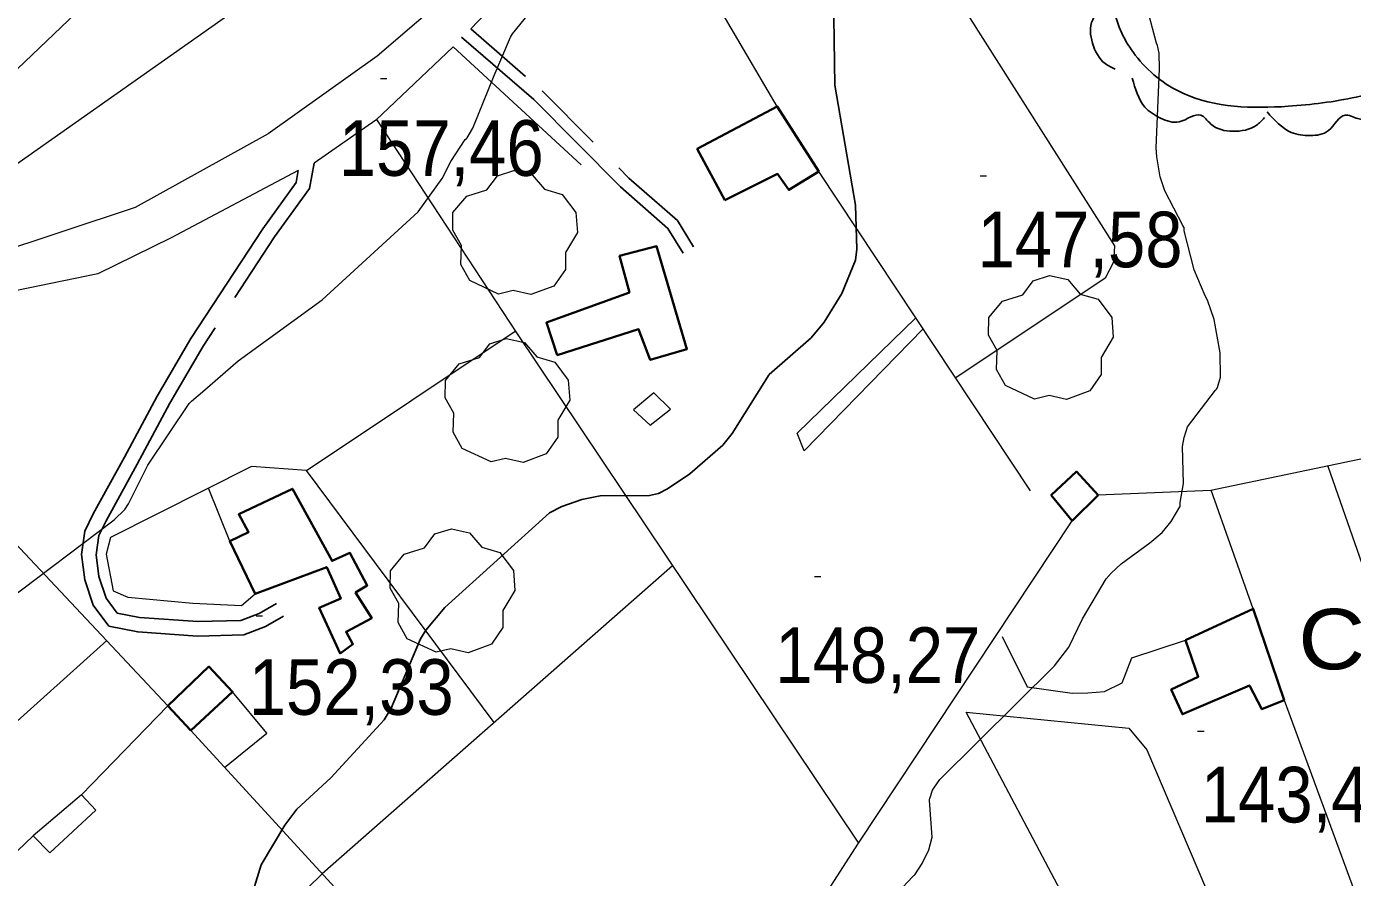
# Model space of a CAD drawing. Extents: x 480269 to 484877, y 4383588 to 4386804.
# Drawn here: x 481094.5 to 481302.9, y 4386070.7 to 4386204.5 of the extents above; entities that cross this region are included whole.
import ezdxf

# ---------------------------------------------------------------- set-up
doc = ezdxf.new("R2010")
doc.units = 0
doc.header["$LTSCALE"] = 3.8
doc.linetypes.add('MEDIUM_DASHED', pattern=[4.5, 3, -1.5])
for name, color, linetype, lineweight in [('27', 7, 'Continuous', 25), ('29', 7, 'Continuous', 13), ('38', 7, 'Continuous', 25), ('47', 7, 'Continuous', 35), ('51', 7, 'Continuous', 13), ('7', 7, 'Continuous', 13), ('8', 7, 'Continuous', 25), ('9', 7, 'Continuous', 13)]:
    doc.layers.add(name, color=color, linetype=linetype, lineweight=lineweight)
doc.layers.add('5', color=7, linetype='Continuous')

msp = doc.modelspace()

# ---------------------------------------------------------------- linework, layer by layer
at = {"layer": '27'}
for points in [[(481320.35, 4386227.93), (481327.1, 4386209.36), (481329.69, 4386201.13), (481328.04, 4386199.61), (481317.88, 4386196.87), (481303.46, 4386193.44), (481292.76, 4386192), (481276.23, 4386194.04), (481268.74, 4386200.02), (481265.37, 4386207.33), (481265.15, 4386217.97), (481261.89, 4386231.76), (481257.97, 4386240.94), (481250.26, 4386263.55), (481243.38, 4386282.87), (481238.59, 4386293.38), (481231.16, 4386310.07), (481228.43, 4386322.5), (481233.94, 4386332.68), (481243.59, 4386341.49), (481255.64, 4386347.7), (481262.44, 4386352.76), (481268, 4386351.6), (481273.52, 4386343.13), (481280.01, 4386327.28), (481288.32, 4386308.12), (481295.44, 4386293.02), (481303.54, 4386274.74), (481320.35, 4386227.93)], [(481265.56, 4386197.83), (481264.01, 4386198.7), (481262.01, 4386201.92), (481262.04, 4386205.61), (481262.88, 4386207.49), (481260.85, 4386210.41), (481260.49, 4386213.38), (481261.41, 4386216.25), (481265.14, 4386219.53)], [(481289.06, 4386190.21), (481287.76, 4386189), (481284.09, 4386188.07), (481280.58, 4386189.23), (481279.05, 4386190.6), (481275.65, 4386189.56), (481272.72, 4386190.12), (481270.26, 4386191.88), (481268.27, 4386196.43)], [(481310.87, 4386194.68), (481310.24, 4386193.02), (481307.35, 4386190.57), (481303.69, 4386190.07), (481301.71, 4386190.62), (481299.12, 4386188.19), (481296.24, 4386187.4), (481293.25, 4386187.9), (481289.47, 4386191.11)]]:
    msp.add_spline(points, degree=3, dxfattribs=at)
at = {"layer": '29'}
for points in [[(481168.67, 4386162.47), (481164.13, 4386164.59), (481162.72, 4386167.13), (481162.82, 4386170.11), (481161.45, 4386172.52), (481161.49, 4386175.27), (481163.65, 4386177.87), (481166.84, 4386178.87), (481168.49, 4386181.06), (481171.06, 4386181.89), (481173.92, 4386181.24), (481175.87, 4386178.97), (481178.68, 4386178.15), (481180.81, 4386175.3), (481181.05, 4386172.17), (481179.17, 4386169.02), (481179.17, 4386166.34), (481177.35, 4386163.73), (481173.73, 4386162.39), (481170.96, 4386163.02)], [(481252.89, 4386145.97), (481248.35, 4386148.09), (481246.94, 4386150.63), (481247.04, 4386153.61), (481245.67, 4386156.02), (481245.71, 4386158.77), (481247.87, 4386161.37), (481251.06, 4386162.37), (481252.71, 4386164.56), (481255.28, 4386165.39), (481258.14, 4386164.74), (481260.09, 4386162.47), (481262.9, 4386161.65), (481265.03, 4386158.8), (481265.27, 4386155.67), (481263.39, 4386152.52), (481263.39, 4386149.84), (481261.57, 4386147.23), (481257.95, 4386145.89), (481255.18, 4386146.52)], [(481167.48, 4386136.08), (481162.94, 4386138.2), (481161.53, 4386140.74), (481161.63, 4386143.72), (481160.26, 4386146.13), (481160.3, 4386148.88), (481162.46, 4386151.48), (481165.65, 4386152.48), (481167.3, 4386154.67), (481169.87, 4386155.5), (481172.73, 4386154.85), (481174.68, 4386152.58), (481177.49, 4386151.76), (481179.62, 4386148.91), (481179.86, 4386145.78), (481177.98, 4386142.63), (481177.98, 4386139.95), (481176.16, 4386137.34), (481172.54, 4386136), (481169.77, 4386136.63)], [(481158.85, 4386106.16), (481154.31, 4386108.28), (481152.9, 4386110.82), (481153, 4386113.8), (481151.63, 4386116.21), (481151.67, 4386118.96), (481153.83, 4386121.56), (481157.02, 4386122.56), (481158.67, 4386124.75), (481161.24, 4386125.58), (481164.1, 4386124.93), (481166.05, 4386122.66), (481168.86, 4386121.84), (481170.99, 4386118.99), (481171.23, 4386115.86), (481169.35, 4386112.71), (481169.35, 4386110.03), (481167.53, 4386107.42), (481163.91, 4386106.08), (481161.14, 4386106.71)]]:
    msp.add_lwpolyline(points, close=True, dxfattribs=at)
at = {"layer": '38', "linetype": 'MEDIUM_DASHED'}
for points in [[(481164.3, 4386204.15), (481175.5, 4386194.43), (481189.13, 4386180.72), (481196.76, 4386174.04), (481199.3, 4386169.88)], [(481139.7, 4386183.03), (481138.97, 4386179.07), (481133.47, 4386171.47), (481122.23, 4386154.26), (481116.97, 4386145.29), (481111.88, 4386135.73), (481106.97, 4386126.84), (481105.81, 4386124.52), (481105.41, 4386121.49), (481105.83, 4386118.05), (481106.98, 4386114.64), (481108.72, 4386112.32), (481112.25, 4386111.6), (481121.4, 4386110.97), (481128.18, 4386111.14), (481131.02, 4386112.27), (481133.76, 4386113.83)]]:
    msp.add_lwpolyline(points, dxfattribs=at)
at = {"layer": '38'}
for points in [[(481162.84, 4386202.89), (481174.19, 4386193.04), (481187.82, 4386179.33), (481195.28, 4386172.79), (481197.68, 4386168.88)], [(481137.19, 4386181.91), (481136.83, 4386179.99), (481131.6, 4386172.75), (481120.3, 4386155.46), (481114.99, 4386146.4), (481109.89, 4386136.81), (481104.96, 4386127.9), (481103.61, 4386125.2), (481103.12, 4386121.5), (481103.61, 4386117.55), (481104.95, 4386113.57), (481107.42, 4386110.27), (481111.94, 4386109.35), (481121.35, 4386108.7), (481128.65, 4386108.88), (481132.01, 4386110.22), (481134.88, 4386111.85)]]:
    msp.add_lwpolyline(points, dxfattribs=at)
at = {"layer": '47'}
for points in [[(481204.22, 4386177.22), (481199.89, 4386185.29), (481212.47, 4386191.97), (481218.98, 4386181.76), (481214.3, 4386178.84), (481212.5, 4386181.35)], [(481177.86, 4386152.84), (481176.18, 4386157.99), (481189.22, 4386162.74), (481187.69, 4386168.49), (481193.5, 4386169.99), (481198.27, 4386153.81), (481192.51, 4386152.11), (481190.68, 4386156.95)], [(481258.82, 4386126.83), (481255.52, 4386130.87), (481259.51, 4386134.56), (481262.89, 4386130.87)], [(481130.4, 4386115.36), (481141.66, 4386119.55), (481143.87, 4386114.58), (481140.46, 4386113.13), (481143.76, 4386105.96), (481145.78, 4386107.43), (481144.69, 4386109.37), (481148.74, 4386111.53), (481146.18, 4386115.57), (481148.03, 4386116.66), (481145.3, 4386121.77), (481142.49, 4386120.52), (481136.26, 4386131.87), (481127.82, 4386127.84), (481129.37, 4386125.04), (481126.44, 4386123.6)], [(481292.15, 4386098.63), (481288.63, 4386097.18), (481286.67, 4386100.93), (481276.15, 4386096.39), (481274.4, 4386100.27), (481278.63, 4386102.29), (481276.65, 4386108.04), (481287.28, 4386113)], [(481120.27, 4386093.83), (481116.69, 4386097.73), (481123.14, 4386103.9), (481126.87, 4386099.93)]]:
    msp.add_lwpolyline(points, close=True, dxfattribs=at)
at = {"layer": '47', "lineweight": 13}
for points in [[(481195.66, 4386144.35), (481193.05, 4386146.95), (481189.86, 4386144.29), (481192.47, 4386141.85)], [(481095.51, 4386077.3), (481098.14, 4386074.59), (481105.38, 4386081.32), (481103.13, 4386083.72)]]:
    msp.add_lwpolyline(points, close=True, dxfattribs=at)
at = {"layer": '51'}
for p, q in [((481212.47, 4386191.97), (481196.86, 4386218.52)), ((481252.28, 4386131.52), (481218.98, 4386181.76)), ((481138.48, 4386134.72), (481171.29, 4386156.65)), ((481126.44, 4386123.6), (481123.07, 4386131.96)), ((481287.28, 4386113), (481280.66, 4386131.62)), ((481292.15, 4386098.63), (481313.58, 4386040.31))]:
    msp.add_line(p, q, dxfattribs=at)
for points in [[(481189.43, 4386238.35), (481184.8, 4386233.8), (481167.77, 4386215.52), (481149.6, 4386199.89), (481132.43, 4386187.68), (481111.54, 4386176.08), (481088.62, 4386168.47), (481055.25, 4386162.19), (481090.79, 4386195.75), (481138.64, 4386241.42), (481164.71, 4386260.99), (481179.45, 4386241.02)], [(481213.22, 4386252.41), (481265.46, 4386170.05), (481265.32, 4386167.49), (481264.01, 4386164.98), (481240.52, 4386149.28)], [(481187.53, 4386230.7), (481179.87, 4386220.51), (481164.3, 4386204.15)], [(481181.65, 4386182.78), (481161.51, 4386201.36), (481149.37, 4386189.79), (481139.7, 4386183.03)], [(481149.5, 4386189.92), (481171.46, 4386156.38), (481225.22, 4386076.14), (481258.82, 4386126.83)], [(481137.19, 4386181.91), (481117.19, 4386171.32), (481105.67, 4386165.67), (481083.75, 4386161.16), (481058.74, 4386156.51), (481055.51, 4386154.8), (481040.51, 4386142.05), (481024.04, 4386125.12), (481017.98, 4386120.55), (481018.16, 4386119.27), (481053.02, 4386082.5)], [(481235.41, 4386156.99), (481216.7, 4386137.83), (481215.61, 4386140.62), (481234.27, 4386158.71)], [(481353.68, 4386144.85), (481315.46, 4386138.85), (481280.62, 4386131.6), (481262.89, 4386130.87)], [(481167.95, 4386095.08), (481138.48, 4386134.72), (481129.85, 4386135.35), (481107.65, 4386124.22), (481107.01, 4386121.57), (481108.1, 4386115.81), (481110.41, 4386114.82), (481120.6, 4386113.85), (481128.26, 4386113.48), (481130.4, 4386115.36)], [(481299.01, 4386135.43), (481329.29, 4386048.69), (481313.76, 4386040.4), (481294.64, 4386030.93), (481284.32, 4386031.77), (481257.58, 4386020.54), (481256.46, 4386019.16)], [(481103.13, 4386083.72), (481116.69, 4386097.73), (481090.99, 4386125.1)], [(481196, 4386119.76), (481140.93, 4386071.31), (481117.79, 4386048.65)], [(481073.85, 4386071.81), (481075.02, 4386075.02), (481075.2, 4386079.34), (481107.07, 4386107.99)], [(481247.81, 4386108.65), (481251.72, 4386100.71), (481258.83, 4386099.72), (481261.27, 4386099.78), (481263.92, 4386099.97), (481266.66, 4386101.34), (481268.18, 4386105.28), (481276.65, 4386108.04)], [(481125.6, 4386088.03), (481132.23, 4386093.45), (481126.87, 4386099.93)], [(481220.5, 4386017.44), (481228.65, 4386022.49), (481258.46, 4386065.93), (481242.17, 4386096.72), (481267.74, 4386094.19), (481270.54, 4386090.81), (481295.8, 4386031.51)], [(481120.27, 4386093.83), (481188.64, 4386019.26), (481225.22, 4386076.14)], [(481058.01, 4386077.88), (481076.11, 4386058.8), (481095.51, 4386077.3)]]:
    msp.add_lwpolyline(points, dxfattribs=at)
at = {"layer": '7'}
for p, q in [((481150.09, 4386196.37), (481151.09, 4386196.37)), ((481244.36, 4386181.05), (481245.36, 4386181.05)), ((481218.32, 4386118.06), (481219.32, 4386118.06)), ((481130.55, 4386111.86), (481131.55, 4386111.86)), ((481278.54, 4386093.76), (481279.54, 4386093.76))]:
    msp.add_line(p, q, dxfattribs=at)
at = {"layer": '8'}
msp.add_lwpolyline([(481221.27, 4386213.07), (481221.54, 4386195.32), (481224.76, 4386176.45), (481224.98, 4386169.54), (481224.75, 4386167.8), (481222.64, 4386162.57), (481219.85, 4386158.06), (481217.82, 4386155.61), (481211.2, 4386149.81), (481205.36, 4386140.55), (481203.9, 4386138.71), (481198.7, 4386134.22), (481195.23, 4386131.83), (481193.8, 4386131.12), (481192.4, 4386130.81), (481184.64, 4386130.73), (481181.75, 4386130.15), (481178.6, 4386129.05), (481176.69, 4386128.08), (481160.24, 4386113.19), (481157.23, 4386109.6), (481156.41, 4386108.28), (481151.78, 4386097.37), (481150.68, 4386095.51), (481142.31, 4386086.38), (481136.96, 4386081.46), (481135.05, 4386078.98), (481131.35, 4386072.71), (481127.77, 4386061.13)], dxfattribs=at)
at = {"layer": '9'}
for points in [[(481082.1, 4386175.35), (481128.74, 4386208.16), (481149.72, 4386228.72), (481151.72, 4386232), (481152.77, 4386234.57), (481154.53, 4386250.37), (481152.42, 4386261.86), (481151.97, 4386279.59), (481154.14, 4386296.85), (481149.19, 4386347.39), (481148.62, 4386350.12), (481148.44, 4386350.72)], [(481091.3, 4386114.2), (481108.23, 4386126.96), (481109.92, 4386128.62), (481110.48, 4386129.5), (481113.54, 4386135.55), (481120.03, 4386145.27), (481120.4, 4386145.65), (481122.12, 4386147.09), (481127.74, 4386151.95), (481140.94, 4386161.54), (481156.01, 4386175.41), (481159.8, 4386180.63), (481161.18, 4386183.3), (481163.43, 4386186.75), (481163.64, 4386186.93), (481163.73, 4386187.06), (481164.62, 4386188.55), (481167.95, 4386196.83), (481170.53, 4386202.86), (481170.84, 4386203.4), (481176.07, 4386209.91)], [(481276.4, 4386172.93), (481276.39, 4386172.97), (481276.21, 4386173.23), (481273.38, 4386178.72), (481272.63, 4386180.89), (481272.13, 4386184.03), (481272.04, 4386185.47), (481272.52, 4386197.86), (481272.48, 4386200.36), (481272.47, 4386200.37), (481272.23, 4386201.56), (481272.08, 4386201.94), (481270.32, 4386208.4)], [(481223.62, 4386060.06), (481233.71, 4386070.83), (481233.95, 4386071.06), (481234.06, 4386071.12), (481234.1, 4386071.16), (481235.24, 4386072.96), (481236.27, 4386075.1), (481236.83, 4386077.06), (481236.39, 4386082.82), (481236.41, 4386083.03), (481236.44, 4386083.13), (481236.89, 4386084.45), (481237.07, 4386084.79), (481238.04, 4386086.12), (481256.04, 4386104), (481258.3, 4386106.93), (481260.46, 4386111.38), (481264.17, 4386117.71), (481264.95, 4386118.6), (481266.52, 4386120.04), (481271.02, 4386123.33), (481272.96, 4386124.99), (481274.38, 4386126.72), (481275.73, 4386129.01), (481275.77, 4386129.09), (481275.78, 4386129.12), (481275.78, 4386129.16), (481275.77, 4386129.3), (481275.79, 4386129.68), (481276.3, 4386132.67), (481276.15, 4386138.52), (481276.43, 4386139.94), (481276.94, 4386141.59), (481281.32, 4386147.34), (481281.48, 4386147.51), (481281.61, 4386147.69), (481281.65, 4386147.79), (481282.12, 4386149.41), (481282.12, 4386149.43), (481282.12, 4386149.44), (481282.12, 4386149.46), (481282.07, 4386153.22), (481281.14, 4386158.45), (481280.11, 4386161.49), (481279.71, 4386162.17), (481277.97, 4386166.28), (481276.43, 4386172.41), (481276.41, 4386172.89), (481276.4, 4386172.93)]]:
    msp.add_lwpolyline(points, dxfattribs=at)

# ---------------------------------------------------------------- texts
at = {"layer": '5', "width": 1.15}
msp.add_text('Can Vermell', height=9.5, dxfattribs=at).set_placement((481294.34, 4386103.47))
at = {"layer": '7', "width": 0.9}
for s, p in [('157,46', (481143.55, 4386181.06)), ('147,58', (481243.95, 4386166.68)), ('148,27', (481212.17, 4386101.32)), ('152,33', (481129.4, 4386096.31)), ('143,47', (481279.04, 4386079.39))]:
    msp.add_text(s, height=8.75, dxfattribs=at).set_placement(p)

doc.saveas('drawing.dxf')
